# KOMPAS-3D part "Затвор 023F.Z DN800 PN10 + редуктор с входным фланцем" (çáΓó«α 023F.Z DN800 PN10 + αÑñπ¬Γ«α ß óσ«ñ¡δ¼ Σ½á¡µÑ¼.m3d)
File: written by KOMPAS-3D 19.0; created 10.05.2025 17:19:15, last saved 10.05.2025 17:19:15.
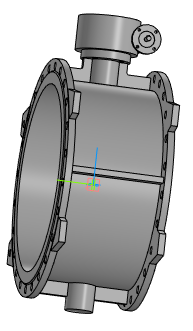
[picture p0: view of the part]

Document properties: Полное имя файла: Затвор 023F.Z DN800 PN10 + редуктор с входным фланцем.a3d

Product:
- Part/product: Затвор 023F.Z DN800 PN10 + редуктор с входным фланцем
    Масса: 746.959

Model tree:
1. Операция без истории:1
